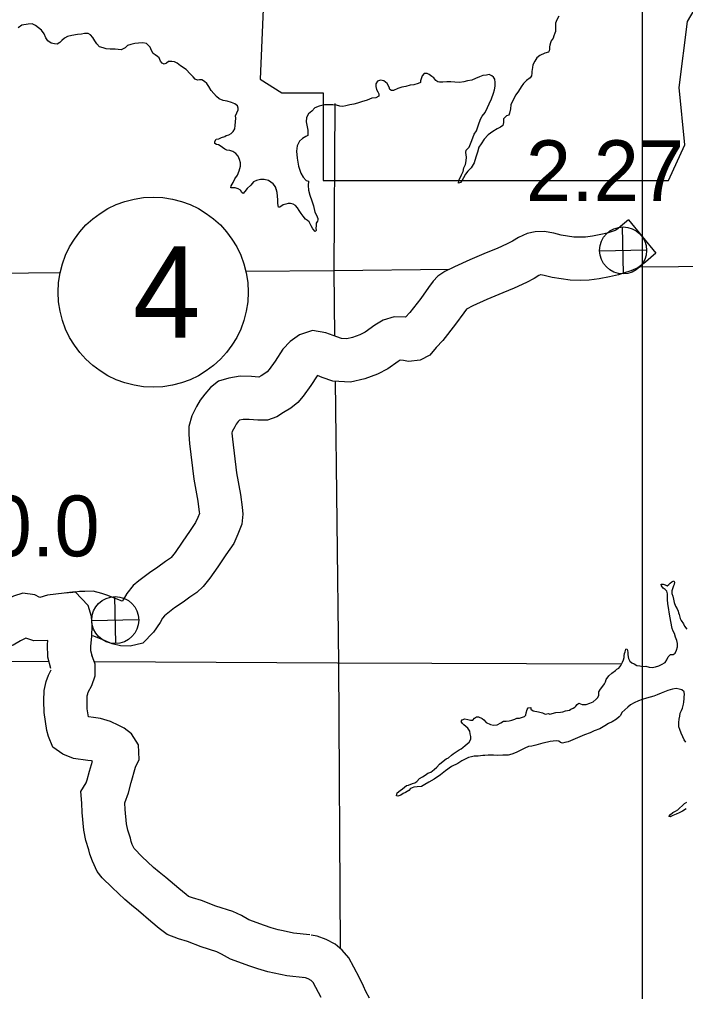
# Model space of a CAD drawing. Extents: x 77230 to 630905, y 790554 to 1662844.
# Drawn here: x 303084 to 312337, y 1564948 to 1578451 of the extents above; entities that cross this region are included whole.
import ezdxf

# ---------------------------------------------------------------- set-up
doc = ezdxf.new("R2010")
doc.units = 0
for name, color, linetype in [('Level 16', 7, 'Continuous'), ('Level 17', 7, 'Continuous'), ('Level 22', 7, 'Continuous'), ('Level 24', 7, 'Continuous'), ('Level 28', 7, 'Continuous'), ('Level 31', 7, 'Continuous'), ('Level 33', 7, 'Continuous'), ('Level 34', 7, 'Continuous')]:
    doc.layers.add(name, color=color, linetype=linetype)

msp = doc.modelspace()

# ---------------------------------------------------------------- linework, layer by layer
at = {"layer": 'Level 16'}
for points in [[(307464, 1577281), (307451, 1574961), (307461, 1574057)], [(311693, 1575013), (312786, 1575026), (316732, 1575056)], [(302343, 1574924), (303639, 1574935)], [(306226, 1574955), (307449, 1574965), (309057, 1574983)], [(307469, 1573431), (307516, 1569506), (307541, 1565548)], [(303494, 1569529), (302249, 1569536), (297070, 1569566), (294654, 1569590)], [(311439, 1569493), (307502, 1569508), (304131, 1569526)]]:
    msp.add_lwpolyline(points, dxfattribs=at)
at = {"layer": 'Level 17'}
for points in [[(310575, 1578497), (310547, 1578445), (310532, 1578400), (310530, 1578370), (310528, 1578320), (310531, 1578284), (310519, 1578258), (310509, 1578224), (310496, 1578192), (310472, 1578156), (310462, 1578124), (310452, 1578094), (310447, 1578072), (310449, 1578040), (310441, 1578017), (310431, 1577995), (310380, 1577983), (310312, 1577950), (310272, 1577916), (310245, 1577870), (310217, 1577820), (310212, 1577782), (310202, 1577729), (310200, 1577703), (310198, 1577667), (310179, 1577641), (310127, 1577601), (310086, 1577560), (310054, 1577516), (310017, 1577456), (309981, 1577402), (309944, 1577333), (309912, 1577267), (309903, 1577211), (309891, 1577147), (309882, 1577123), (309848, 1577110), (309810, 1577068), (309807, 1577018), (309799, 1576976), (309767, 1576956), (309720, 1576931), (309660, 1576893), (309594, 1576846), (309539, 1576788), (309500, 1576725), (309466, 1576675), (309445, 1576607), (309423, 1576539), (309402, 1576458), (309361, 1576390), (309313, 1576344), (309282, 1576301), (309250, 1576253), (309228, 1576211), (309211, 1576187), (309183, 1576177), (309187, 1576215), (309224, 1576293), (309247, 1576339), (309257, 1576391), (309279, 1576437), (309288, 1576486), (309296, 1576536), (309291, 1576570), (309285, 1576604), (309289, 1576634), (309330, 1576678), (309360, 1576744), (309381, 1576806), (309401, 1576855), (309434, 1576903)], [(304245, 1578058), (304197, 1578070), (304161, 1578110), (304131, 1578155), (304104, 1578199), (304072, 1578237), (304038, 1578255), (303988, 1578254), (303948, 1578246), (303890, 1578244), (303813, 1578229), (303751, 1578215), (303709, 1578192), (303674, 1578160), (303646, 1578132), (303610, 1578109), (303570, 1578111), (303526, 1578123), (303480, 1578152), (303452, 1578194), (303429, 1578252), (303389, 1578300), (303351, 1578333), (303307, 1578365), (303263, 1578389), (303207, 1578384), (303117, 1578370), (303066, 1578335)], [(306666, 1576048), (306643, 1576126), (306609, 1576166), (306545, 1576212), (306485, 1576229), (306433, 1576229), (306377, 1576212), (306335, 1576194), (306298, 1576148), (306248, 1576101), (306217, 1576061), (306191, 1576033), (306171, 1576045), (306153, 1576078), (306123, 1576100), (306082, 1576114), (306045, 1576114), (306019, 1576111), (306024, 1576141), (306054, 1576186), (306078, 1576236), (306111, 1576290), (306138, 1576346), (306154, 1576411), (306156, 1576459), (306143, 1576505), (306121, 1576554), (306089, 1576588), (306047, 1576618), (306007, 1576632), (305967, 1576637), (305935, 1576647), (305906, 1576671), (305874, 1576697), (305848, 1576710), (305820, 1576714), (305798, 1576726), (305798, 1576754), (305816, 1576788), (305852, 1576794), (305893, 1576811), (305935, 1576827), (305957, 1576839), (305993, 1576850), (306025, 1576866), (306054, 1576896), (306074, 1576932), (306080, 1576978), (306087, 1577030), (306089, 1577078), (306086, 1577112), (306102, 1577155), (306122, 1577193), (306124, 1577217), (306111, 1577251), (306075, 1577278), (306029, 1577298), (305969, 1577314), (305913, 1577327), (305859, 1577349), (305823, 1577379), (305785, 1577424), (305748, 1577464), (305714, 1577520), (305686, 1577562), (305656, 1577591), (305618, 1577611), (305586, 1577611), (305558, 1577609), (305526, 1577620), (305499, 1577654), (305457, 1577694), (305399, 1577755), (305323, 1577805), (305274, 1577842), (305240, 1577862), (305202, 1577868), (305153, 1577865), (305129, 1577843), (305093, 1577831), (305067, 1577843), (305043, 1577873), (305024, 1577916), (305002, 1577936), (304970, 1577958), (304942, 1577978), (304918, 1578018), (304902, 1578066), (304881, 1578085), (304847, 1578115), (304797, 1578127), (304737, 1578122), (304686, 1578116), (304632, 1578101), (304586, 1578091), (304552, 1578057), (304495, 1578028), (304413, 1578036), (304343, 1578037), (304289, 1578043), (304245, 1578058)], [(309434, 1576903), (309450, 1576961), (309471, 1577017), (309493, 1577075), (309511, 1577106), (309554, 1577158), (309585, 1577226), (309607, 1577278), (309640, 1577349), (309668, 1577429), (309683, 1577475), (309693, 1577523), (309692, 1577575), (309686, 1577619), (309670, 1577651), (309644, 1577669), (309608, 1577685), (309570, 1577678), (309522, 1577670), (309476, 1577652), (309417, 1577631), (309367, 1577609), (309309, 1577598), (309259, 1577584), (309196, 1577575), (309134, 1577579), (309078, 1577582), (309022, 1577582), (308964, 1577578), (308920, 1577579), (308894, 1577583), (308870, 1577601), (308840, 1577639), (308814, 1577660), (308776, 1577684), (308746, 1577700), (308706, 1577698), (308680, 1577669), (308664, 1577627), (308655, 1577597), (308655, 1577577), (308621, 1577559), (308561, 1577544), (308513, 1577538), (308452, 1577519), (308396, 1577511), (308338, 1577493), (308281, 1577466), (308253, 1577464), (308231, 1577480), (308220, 1577512), (308192, 1577563), (308146, 1577597), (308098, 1577607), (308060, 1577592), (308034, 1577558), (308033, 1577518), (308043, 1577478), (308061, 1577444)], [(308061, 1577444), (308075, 1577418), (308074, 1577386), (308036, 1577360), (307978, 1577356), (307914, 1577331), (307837, 1577308), (307779, 1577290), (307727, 1577276), (307674, 1577263), (307616, 1577249), (307576, 1577242), (307534, 1577246), (307486, 1577260), (307438, 1577263), (307374, 1577263), (307322, 1577264), (307249, 1577244), (307189, 1577221), (307146, 1577175), (307098, 1577138), (307072, 1577090), (307069, 1577030), (307079, 1576958), (307090, 1576914), (307090, 1576870), (307090, 1576840), (307063, 1576824), (307017, 1576796), (306975, 1576759), (306942, 1576693), (306934, 1576619), (306941, 1576525), (306962, 1576415), (306991, 1576315), (307023, 1576259), (307065, 1576214), (307101, 1576204), (307096, 1576146), (307100, 1576078), (307117, 1576008), (307144, 1575930), (307170, 1575862), (307187, 1575774), (307211, 1575731), (307231, 1575687), (307229, 1575667), (307224, 1575649), (307206, 1575619), (307204, 1575583), (307202, 1575552), (307205, 1575520), (307191, 1575506), (307159, 1575544), (307138, 1575586), (307110, 1575638), (307084, 1575660), (307056, 1575675), (307026, 1575717), (306999, 1575757), (306969, 1575797), (306945, 1575833), (306917, 1575866), (306884, 1575884), (306850, 1575894), (306817, 1575896), (306783, 1575887), (306749, 1575877), (306717, 1575851), (306699, 1575841), (306681, 1575844), (306675, 1575894), (306674, 1575944), (306670, 1575994), (306666, 1576048), (306653, 1576090), (306631, 1576136)], [(312153, 1569992), (312132, 1570089), (312113, 1570189), (312099, 1570281), (312092, 1570335), (312086, 1570393), (312087, 1570435), (312085, 1570471), (312077, 1570509), (312054, 1570531), (312028, 1570549), (312002, 1570582), (312000, 1570606), (312026, 1570605), (312052, 1570595), (312080, 1570585), (312106, 1570601), (312125, 1570622), (312145, 1570638), (312173, 1570652), (312183, 1570634), (312177, 1570604), (312170, 1570582), (312156, 1570542), (312146, 1570512), (312147, 1570478), (312159, 1570440), (312169, 1570398), (312180, 1570352), (312198, 1570302), (312218, 1570264), (312235, 1570230), (312241, 1570210), (312249, 1570185), (312264, 1570129), (312278, 1570101), (312308, 1570057), (312324, 1570025), (312353, 1569981)], [(309384, 1568719), (309403, 1568747), (309433, 1568765), (309461, 1568764), (309513, 1568740), (309535, 1568720), (309569, 1568687), (309626, 1568659), (309671, 1568650), (309719, 1568654), (309769, 1568680), (309809, 1568703), (309847, 1568705), (309886, 1568710), (309922, 1568716), (309966, 1568730), (309994, 1568743), (310030, 1568745), (310099, 1568768), (310117, 1568788), (310123, 1568818), (310138, 1568864), (310152, 1568888), (310188, 1568895), (310188, 1568871), (310220, 1568849), (310294, 1568832), (310348, 1568818), (310388, 1568802), (310434, 1568809), (310450, 1568801), (310534, 1568824), (310602, 1568828), (310631, 1568833), (310671, 1568845), (310725, 1568858), (310745, 1568868), (310777, 1568882), (310800, 1568898), (310814, 1568914), (310830, 1568935), (310856, 1568953), (310902, 1568935), (310958, 1568936), (311007, 1568952), (311053, 1568971), (311097, 1569011), (311116, 1569031), (311130, 1569063), (311134, 1569110), (311157, 1569150), (311187, 1569190), (311212, 1569224), (311224, 1569248), (311232, 1569283), (311269, 1569331), (311313, 1569371), (311362, 1569406), (311384, 1569424), (311410, 1569442), (311438, 1569477), (311463, 1569521), (311473, 1569557), (311482, 1569587), (311486, 1569611), (311490, 1569645), (311498, 1569665), (311505, 1569703), (311521, 1569709), (311531, 1569692), (311534, 1569654), (311536, 1569626), (311546, 1569576), (311561, 1569538), (311591, 1569514), (311621, 1569498), (311659, 1569479), (311701, 1569471), (311745, 1569463), (311785, 1569468), (311833, 1569454), (311875, 1569449), (311921, 1569459), (311964, 1569470), (312004, 1569490), (312054, 1569520), (312077, 1569557), (312097, 1569597), (312109, 1569613), (312128, 1569629), (312166, 1569630), (312194, 1569650), (312210, 1569690), (312227, 1569736), (312227, 1569782), (312214, 1569822), (312196, 1569872), (312184, 1569920), (312163, 1569954), (312153, 1569992)], [(312339, 1568411), (312317, 1568446), (312298, 1568488), (312276, 1568536), (312256, 1568590), (312243, 1568626), (312243, 1568684), (312248, 1568730), (312256, 1568772), (312264, 1568814), (312279, 1568852), (312295, 1568886), (312310, 1568939), (312312, 1568967), (312318, 1569019), (312319, 1569047), (312321, 1569071), (312317, 1569113), (312285, 1569140), (312249, 1569148), (312205, 1569156), (312157, 1569147), (312091, 1569131), (312043, 1569110), (311996, 1569094), (311942, 1569071), (311896, 1569051), (311847, 1569036), (311793, 1569022), (311735, 1569003), (311683, 1568987), (311624, 1568958), (311572, 1568930), (311533, 1568897), (311491, 1568863), (311453, 1568824), (311434, 1568784), (311416, 1568762), (311377, 1568730)], [(311377, 1568730), (311317, 1568695), (311265, 1568669), (311216, 1568638), (311148, 1568595), (311069, 1568567), (311011, 1568540), (310934, 1568515), (310836, 1568472), (310771, 1568446), (310705, 1568417), (310661, 1568405), (310629, 1568398), (310599, 1568406), (310577, 1568426), (310539, 1568430), (310497, 1568425), (310458, 1568419), (310418, 1568410), (310354, 1568398), (310290, 1568379), (310255, 1568369), (310201, 1568358), (310153, 1568350), (310103, 1568327), (310038, 1568295), (309982, 1568268), (309923, 1568244), (309875, 1568231), (309799, 1568231), (309729, 1568228), (309667, 1568233), (309595, 1568233), (309550, 1568226), (309520, 1568226), (309456, 1568219), (309402, 1568217), (309364, 1568210), (309322, 1568200), (309277, 1568176), (309227, 1568151), (309172, 1568117), (309086, 1568076), (309001, 1568013), (308932, 1567960), (308846, 1567899), (308773, 1567855), (308717, 1567824), (308668, 1567794), (308608, 1567793), (308562, 1567787), (308516, 1567768), (308495, 1567740), (308445, 1567712), (308413, 1567699), (308382, 1567677), (308342, 1567663), (308322, 1567668), (308333, 1567709), (308373, 1567739), (308405, 1567763), (308432, 1567789), (308460, 1567808), (308490, 1567816), (308542, 1567837), (308576, 1567847), (308603, 1567865), (308641, 1567908), (308685, 1567930), (308720, 1567954), (308756, 1567979), (308800, 1567997), (308843, 1568031), (308883, 1568064), (308918, 1568108), (308972, 1568149), (309013, 1568179), (309043, 1568193), (309087, 1568232), (309111, 1568252), (309138, 1568270), (309190, 1568303), (309222, 1568317), (309245, 1568337), (309275, 1568364), (309303, 1568390), (309332, 1568414), (309352, 1568454), (309354, 1568490), (309347, 1568528), (309339, 1568566), (309313, 1568604), (309285, 1568628), (309258, 1568654), (309240, 1568671), (309222, 1568699), (309236, 1568723), (309272, 1568734), (309312, 1568726), (309348, 1568719), (309384, 1568719)], [(312345, 1567484), (312294, 1567452), (312250, 1567429), (312208, 1567413), (312159, 1567394), (312121, 1567376), (312105, 1567378), (312127, 1567408), (312162, 1567433), (312198, 1567453), (312230, 1567473), (312252, 1567495), (312293, 1567530), (312323, 1567558), (312355, 1567578)]]:
    msp.add_lwpolyline(points, dxfattribs=at)
at = {"layer": 'Level 22'}
for points in [[(311542, 1575667), (311462, 1575600), (311402, 1575546), (311370, 1575523), (311361, 1575518), (311305, 1575501), (311246, 1575482), (311161, 1575462), (311042, 1575441), (310948, 1575427), (310880, 1575425), (310786, 1575428), (310695, 1575441), (310608, 1575453), (310509, 1575480), (310371, 1575506), (310250, 1575501), (310136, 1575477), (310015, 1575423), (309935, 1575373), (309859, 1575333), (309719, 1575267), (309569, 1575208), (309339, 1575110), (309128, 1575016), (308991, 1574948), (308894, 1574883), (308831, 1574814), (308768, 1574726), (308659, 1574576), (308507, 1574380), (308446, 1574315), (308288, 1574319), (308135, 1574272), (308021, 1574205), (307885, 1574109), (307812, 1574071), (307712, 1574034), (307633, 1574016), (307557, 1574020), (307494, 1574042), (307342, 1574099), (307153, 1574128), (306973, 1574069), (306846, 1573979), (306742, 1573870), (306637, 1573703), (306553, 1573590), (306526, 1573558), (306506, 1573541), (306440, 1573502), (306411, 1573483), (306307, 1573491), (306148, 1573495), (305992, 1573468), (305848, 1573424), (305739, 1573340), (305658, 1573245), (305594, 1573163), (305544, 1573075), (305478, 1572943), (305438, 1572796), (305435, 1572687), (305445, 1572560), (305507, 1572063), (305561, 1571760), (305581, 1571607), (305583, 1571587), (305562, 1571532), (305531, 1571462), (305457, 1571351), (305346, 1571188), (305246, 1571047), (305192, 1570977), (305181, 1570966), (305111, 1570922), (305008, 1570844), (304889, 1570763), (304744, 1570654), (304666, 1570586), (304576, 1570476), (304527, 1570390), (304513, 1570370), (304429, 1570405), (304297, 1570454), (304228, 1570479), (304108, 1570510), (303993, 1570503), (303918, 1570503), (303797, 1570488)], [(311542, 1575667), (311926, 1575205)], [(311926, 1575205), (311855, 1575146), (311780, 1575079), (311674, 1575002), (311576, 1574957), (311488, 1574929), (311407, 1574903), (311281, 1574874), (311137, 1574849), (311000, 1574829), (310881, 1574825), (310736, 1574829), (310611, 1574847), (310486, 1574864), (310373, 1574895), (310327, 1574904), (310325, 1574904), (310323, 1574904), (310297, 1574892), (310235, 1574853), (310128, 1574796), (309957, 1574716), (309797, 1574652), (309578, 1574559), (309384, 1574473), (309294, 1574428), (309292, 1574427), (309255, 1574375), (309139, 1574216), (308964, 1573990), (308873, 1573893), (308784, 1573786), (308650, 1573717), (308488, 1573699), (308418, 1573715), (308374, 1573716), (308345, 1573699), (308199, 1573597), (308058, 1573522), (307883, 1573457), (307683, 1573412), (307439, 1573426), (307290, 1573478), (307222, 1573504), (307218, 1573500), (307133, 1573365), (307024, 1573217), (306952, 1573132), (306854, 1573049), (306753, 1572990), (306660, 1572930), (306528, 1572884), (306397, 1572883), (306276, 1572892), (306192, 1572894), (306140, 1572885), (306122, 1572864), (306094, 1572829), (306074, 1572793), (306041, 1572728), (306035, 1572707), (306035, 1572704), (306042, 1572622), (306100, 1572153), (306154, 1571852), (306177, 1571677), (306187, 1571581), (306172, 1571442), (306116, 1571303), (306060, 1571173), (305953, 1571014), (305839, 1570847), (305730, 1570691), (305638, 1570572), (305550, 1570489), (305453, 1570428), (305358, 1570357), (305239, 1570276), (305122, 1570187), (305098, 1570166), (305073, 1570135), (305039, 1570076), (304948, 1569939), (304799, 1569788), (304623, 1569744), (304488, 1569751), (304372, 1569778), (304209, 1569847), (304102, 1569887)], [(304098, 1569595), (304075, 1569679), (304074, 1569745), (304088, 1569878), (304094, 1570033), (304083, 1570156), (304038, 1570309), (303860, 1570498), (303589, 1570468), (303475, 1570452), (303368, 1570423), (303296, 1570457), (303130, 1570483), (303001, 1570438), (302820, 1570351), (302739, 1570304), (302722, 1570297), (302714, 1570301), (302669, 1570332), (302554, 1570404), (302435, 1570451), (302307, 1570464), (302262, 1570466)], [(303811, 1570489), (303722, 1570483)], [(303520, 1569436), (303477, 1569591), (303473, 1569769), (303479, 1569825), (303285, 1569819), (303173, 1569855), (303101, 1569820), (302999, 1569761), (302865, 1569709), (302725, 1569680), (302583, 1569705), (302488, 1569743), (302410, 1569783), (302343, 1569828), (302288, 1569863), (302265, 1569865), (302234, 1569866)], [(307117, 1565736), (306890, 1565760), (306749, 1565790), (306680, 1565805), (306579, 1565833), (306487, 1565866), (306269, 1565944), (306168, 1566002), (306047, 1566059), (305810, 1566134), (305615, 1566212), (305486, 1566249), (305432, 1566270), (305399, 1566295), (305298, 1566380), (305118, 1566531), (305024, 1566607), (304948, 1566672), (304786, 1566825), (304681, 1566929), (304677, 1566934), (304652, 1566988), (304636, 1567032), (304625, 1567076), (304590, 1567190), (304573, 1567278), (304554, 1567477), (304550, 1567569), (304600, 1567710), (304638, 1567853), (304696, 1568063), (304749, 1568172), (304739, 1568377), (304642, 1568527), (304537, 1568607), (304464, 1568644), (304348, 1568700), (304208, 1568741), (304111, 1568753), (304043, 1568762), (304026, 1568874), (304024, 1568986), (304026, 1569054), (304033, 1569085), (304039, 1569104), (304088, 1569199), (304138, 1569335), (304137, 1569496), (304090, 1569621)], [(307053, 1565139), (306797, 1565167), (306622, 1565203), (306535, 1565223), (306396, 1565261), (306284, 1565302), (306018, 1565397), (305891, 1565469), (305828, 1565499), (305608, 1565568), (305420, 1565643), (305292, 1565680), (305138, 1565741), (305027, 1565824), (304911, 1565921), (304737, 1566067), (304639, 1566146), (304546, 1566227), (304370, 1566393), (304234, 1566526), (304162, 1566617), (304097, 1566759), (304060, 1566858), (304046, 1566918), (304007, 1567044), (303979, 1567191), (303955, 1567436), (303950, 1567565), (303939, 1567728), (304012, 1567847), (304027, 1567888), (304059, 1568009), (304097, 1568148), (304085, 1568151), (304034, 1568158), (303836, 1568184), (303686, 1568247), (303549, 1568342), (303486, 1568489), (303464, 1568572), (303427, 1568824), (303423, 1568988), (303428, 1569128), (303455, 1569253), (303488, 1569343), (303526, 1569417)], [(307948, 1564857), (307896, 1564950), (307865, 1565023), (307808, 1565140), (307729, 1565285), (307661, 1565417), (307567, 1565523), (307470, 1565604), (307343, 1565670), (307221, 1565718), (307137, 1565733)], [(307275, 1564865), (307199, 1565003), (307162, 1565075), (307147, 1565092), (307136, 1565102), (307095, 1565123), (307057, 1565138), (307032, 1565142)]]:
    msp.add_lwpolyline(points, dxfattribs=at)
at = {"layer": 'Level 24'}
msp.add_lwpolyline([(306236, 1583368), (306578, 1581084), (306426, 1577620), (306731, 1577430), (307302, 1577430), (307302, 1576212), (312098, 1576212), (312326, 1576707), (312250, 1577506), (312364, 1578420), (312783, 1579143), (313049, 1579676), (313430, 1580247), (313658, 1580856), (313849, 1581351), (314191, 1581769), (314267, 1582036), (314115, 1582226), (312935, 1582226), (313202, 1582759), (313240, 1583102), (313082, 1583365)], close=True, dxfattribs=at)
at = {"layer": 'Level 28'}
msp.add_line((311736, 1658884), (311736, 1488604), dxfattribs=at)
at = {"layer": 'Level 33'}
msp.add_circle((304942, 1574663), 1320, dxfattribs=at)
at = {"layer": 'Level 34'}
for p, q in [((311477, 1574918), (311462, 1575569)), ((311144, 1575236), (311795, 1575251)), ((304422, 1569783), (304407, 1570434)), ((304089, 1570101), (304740, 1570116))]:
    msp.add_line(p, q, dxfattribs=at)
for centre in [(311469, 1575243), (304415, 1570108)]:
    msp.add_circle(centre, 326, dxfattribs=at)

# ---------------------------------------------------------------- texts
at = {"layer": 'Level 31'}
for s, p in [('2.27', (310119, 1575927)), ('0.0', (302628, 1570993))]:
    msp.add_text(s, height=844.8, dxfattribs=at).set_placement(p)
at = {"layer": 'Level 33'}
msp.add_text('4', height=1267, dxfattribs=at).set_placement((304659, 1574030))

doc.saveas('drawing.dxf')
